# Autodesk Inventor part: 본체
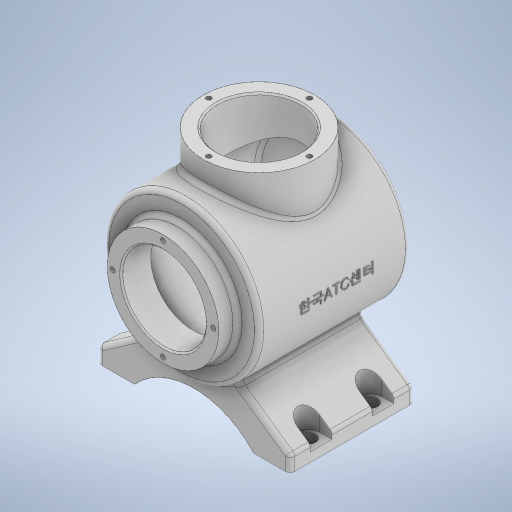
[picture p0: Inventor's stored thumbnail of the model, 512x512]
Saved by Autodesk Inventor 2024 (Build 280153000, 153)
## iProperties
Created: 2023-08
Part Number: 본체
Material: 일반
Document SubType Name: Modeling
Designer: Owner
Density: 1 g/cm^3
Appearance: 기본값
Mass: 480.264 g
Surface Area: 1060.45 cm^2
Volume: 480.264 cm^3
Author: Owner
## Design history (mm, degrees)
sketch "스케치1"
  geometry: L1 (0, 60)-(0, -60); L2 (50, -48.336)-(50, 48); L3 (50, 48)-(36, 48); L4 (36, 48)-(36, 60); L5 (43, -43.887)-(43, 41); L6 (43, 41)-(27, 41); L7 (27, 41)-(27, 60); L8 (36, 60)-(27, 60); A1 r 113 centre (0, 53) between (0, -60) and (50, -48.336); A2 r 106 centre (0, 53) between (0, -53) and (43, -43.887); 3 further points
  constraints: 16 end point, 4 perpendicular, 4 point on circle, 2 centre point, 2 midpoint, 2 vertical, 1 coincident, 1 horizontal, 1 horizontal alignment, 1 point on line, 1 vertical alignment
  dimensions: "d0" = 120 distance of L1.start L1.end; "d4" = 113 radius of A1; "d5" = 100 diameter of L2 L1; "d6" = 72 diameter of L4 L1; "d7" = 7 radial gap between concentric circles of A1 A2; "d8" = 86 diameter of L5 L1; "d9" = 54 diameter of L7 L1; "d10" = 19 distance of L6.end L7.end; "d11" = 108 vertical distance of L1.end L3.end
revolve "회전1" sketch "스케치1" stored, may be unused: angle "d12" = 90 deg
node "작업 평면1"
sketch "스케치2"
  geometry: L1 (-26.694, -42.278)-(-62, -67); L2 (-62, -67)-(-62, -77); L3 (-62, -77)-(-38.5, -77); L4 (38.5, -77)-(62, -77); L5 (62, -77)-(62, -67); L6 (62, -67)-(26.694, -42.278); A1 r 50 centre (0, 0) between (26.694, -42.278) and (-26.694, -42.278) reference; A2 r 52.096 centre (0, -112.096) between (38.5, -77) and (-38.5, -77); 5 further points
  constraints: 12 end point, 4 point on circle, 3 equal length, 2 perpendicular, 1 centre point, 1 horizontal, 1 vertical, 1 vertical alignment, 2 other
  dimensions: "d14" = 55 deg angle of L6 L5; "d15" = 77 distance from line of point (0, 0) L4; "d16" = 10 distance of L4.end L5.end; "d17" = 77 distance of L4.start L3.end; "d19" = 124 distance of L4.end L2.end; "d20" = 55 deg angle of L1 L2; "d21" = 17 vertical distance of L3.end point (0, -60)
extrude "돌출1" join sketch "스케치2" distance "d22" = 80; taper "d23" = 0 deg
node "작업 평면2"
sketch "스케치3"
  geometry: L1 (2.5, 20)-(74.5, 20) reference; C1 r 36 at (38.5, -42); 2 further points
  constraints: 1 centre point, 1 midpoint, 1 vertical alignment
  dimensions: "d25" = 72 diameter of C1; "d26" = 62 distance from line of L1 C1.centre
extrude "돌출2" join sketch "스케치3" stored distance "d27" = 80; taper "d28" = 0 deg
sketch "스케치4"
  geometry: C1 r 36 at (0, 0) reference; C2 r 27 at (0, 0); 1 further point
  constraints: 1 centre point, 1 coincident
  dimensions: "d29" = 54 diameter of C2
extrude "돌출3" cut sketch "스케치4" stored distance "d30" = 10; taper "d31" = 0 deg
sketch "스케치5"
  geometry: L1 (23.5, 0)-(23.5, -80) reference; L2 (0, 0)-(23.5, 0) reference; 3 further points
  dimensions: "d32" = 8 distance from line of point (15.5, -20) L1; "d33" = 20 distance from line of L2 point (15.5, -20); "d34" = 40 distance of point (15.5, -20) point (15.5, -60); "d35" = 8 distance from line of L1 point (15.5, -60)
hole "구멍1" sketch "스케치5" at (15.5, -20), (15.5, -60) diameter "d36" = 9; stored, may be unused: countersink angle "d40" = 90 deg, drill point angle "d42" = 0 deg; dims "d37" = 8, "d38" = 4, "d39" = 2, "d41" = 6
node "작업 평면3"
sketch "스케치6"
  geometry: L1 (-15.5, -13)-(-23.5, -13); L2 (-23.5, 0)-(-23.5, -80) reference; L3 (-15.5, -27)-(-23.5, -27); L4 (-15.5, -53)-(-23.5, -53); L5 (-15.5, -67)-(-23.5, -67); C1 r 4.5 at (-15.5, -20) reference; C2 r 4.5 at (-15.5, -60) reference; A1 r 7 centre (-15.5, -20) between (-15.5, -13) and (-15.5, -27); A2 r 7 centre (-15.5, -60) between (-15.5, -53) and (-15.5, -67); 1 further point
  constraints: 8 end point, 4 point on circle, 4 point on line, 4 tangent, 2 centre point, 2 coincident, 2 perpendicular, 1 horizontal, 1 parallel
  dimensions: "d44" = 14 diameter of A1; "d45" = 14 diameter of A2
extrude "돌출4" cut sketch "스케치6" stored distance "d46" = 10; taper "d47" = 0 deg
sketch "스케치7"
  geometry: 2 further points
  constraints: 1 vertical alignment
  dimensions: "d48" = 32.5 distance of point (0, 32.5) point (0, 0)
hole "구멍2" sketch "스케치7" at (0, 32.5) diameter "d49" = 3.242; stored, may be unused: countersink angle "d53" = 90 deg, drill point angle "d55" = 118 deg; dims "d50" = 8, "d51" = 4, "d52" = 2, "d54" = 10
sketch "스케치8"
  geometry: C1 r 27 at (0, 0) reference; C2 r 36 at (0, 0) reference; 2 further points
  constraints: 1 horizontal alignment
  dimensions: "d59" = 32.5 distance of point (-32.5, 0) C1.centre
hole "구멍3" sketch "스케치8" at (-32.5, 0) diameter "d60" = 3.242; stored, may be unused: countersink angle "d64" = 90 deg, drill point angle "d66" = 118 deg; dims "d61" = 8, "d62" = 4, "d63" = 2, "d65" = 10
node "작업 평면4"
sketch "스케치9"
  geometry: L1 (-36, 60.168)-(36, 60.168) reference; 3 further points
  constraints: 1 midpoint, 1 vertical alignment, 1 other
  dimensions: "d70" = 62 distance from line of L1 point (0, -1.832)
feature "엠보싱1" sketch "스케치9" dims "d0" = 120, "d4" = 113, "d5" = 100, "d6" = 72, "d7" = 7, "d8" = 86, "d9" = 54, "d10" = 19, "d11" = 108, "d14" = 55 deg, "d15" = 77, "d16" = 10, "d17" = 77, "d19" = 124, "d20" = 55 deg, "d21" = 17, "d71" = 0.5, "d72" = 0
fillet "모깎기1" dims "d73" = 3
fillet "모깎기2" dims "d74" = 3
fillet "모깎기3" dims "d75" = 3
fillet "모깎기4" dims "d76" = 3
chamfer "모따기1" distance "d77" = 1; stored, may be unused: second distance "d78" = 2, angle "d79" = 45 deg
fillet "모깎기5" dims "d80" = 3
feature "̫耀̭耀̯耀̱耀̳耀̵耀̷耀̹耀" dims "d0" = 120, "d4" = 113, "d5" = 100, "d6" = 72, "d7" = 7, "d8" = 86, "d9" = 54, "d10" = 19, "d11" = 108, "d12" = 90 deg, "d13" = -20, "d14" = 55 deg, "d15" = 77, "d16" = 10, "d17" = 77, "d19" = 124, "d20" = 55 deg, "d21" = 17, "d22" = 80, "d23" = 0, "d24" = -142, "d25" = 72, "d26" = 62, "d27" = 80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
node "솔리드1"
mirror "미러1"
pattern_circular "원형 패턴1" dims angle "d57" = 360 deg
pattern_circular "원형 패턴2" dims angle "d68" = 360 deg
node "투영된 루프1"
feature "A9D066F2-1C7D-4E18-AEED-F7BC21143FA4" dims "d36" = 9, "d37" = 8, "d38" = 4, "d39" = 2, "d40" = 90 deg, "d41" = 6, "d42" = 0
